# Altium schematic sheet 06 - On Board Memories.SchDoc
size B; CompanyName: Microchip Technology Inc.; Organization: Microchip Technology; Address1: 2355 West Chandler Blvd.; Address2: Chandler, AZ  85224; Address4: USA; DocumentNumber: 6; SheetNumber: 6; SheetTotal: 13; SheetTitle: On Board Memories
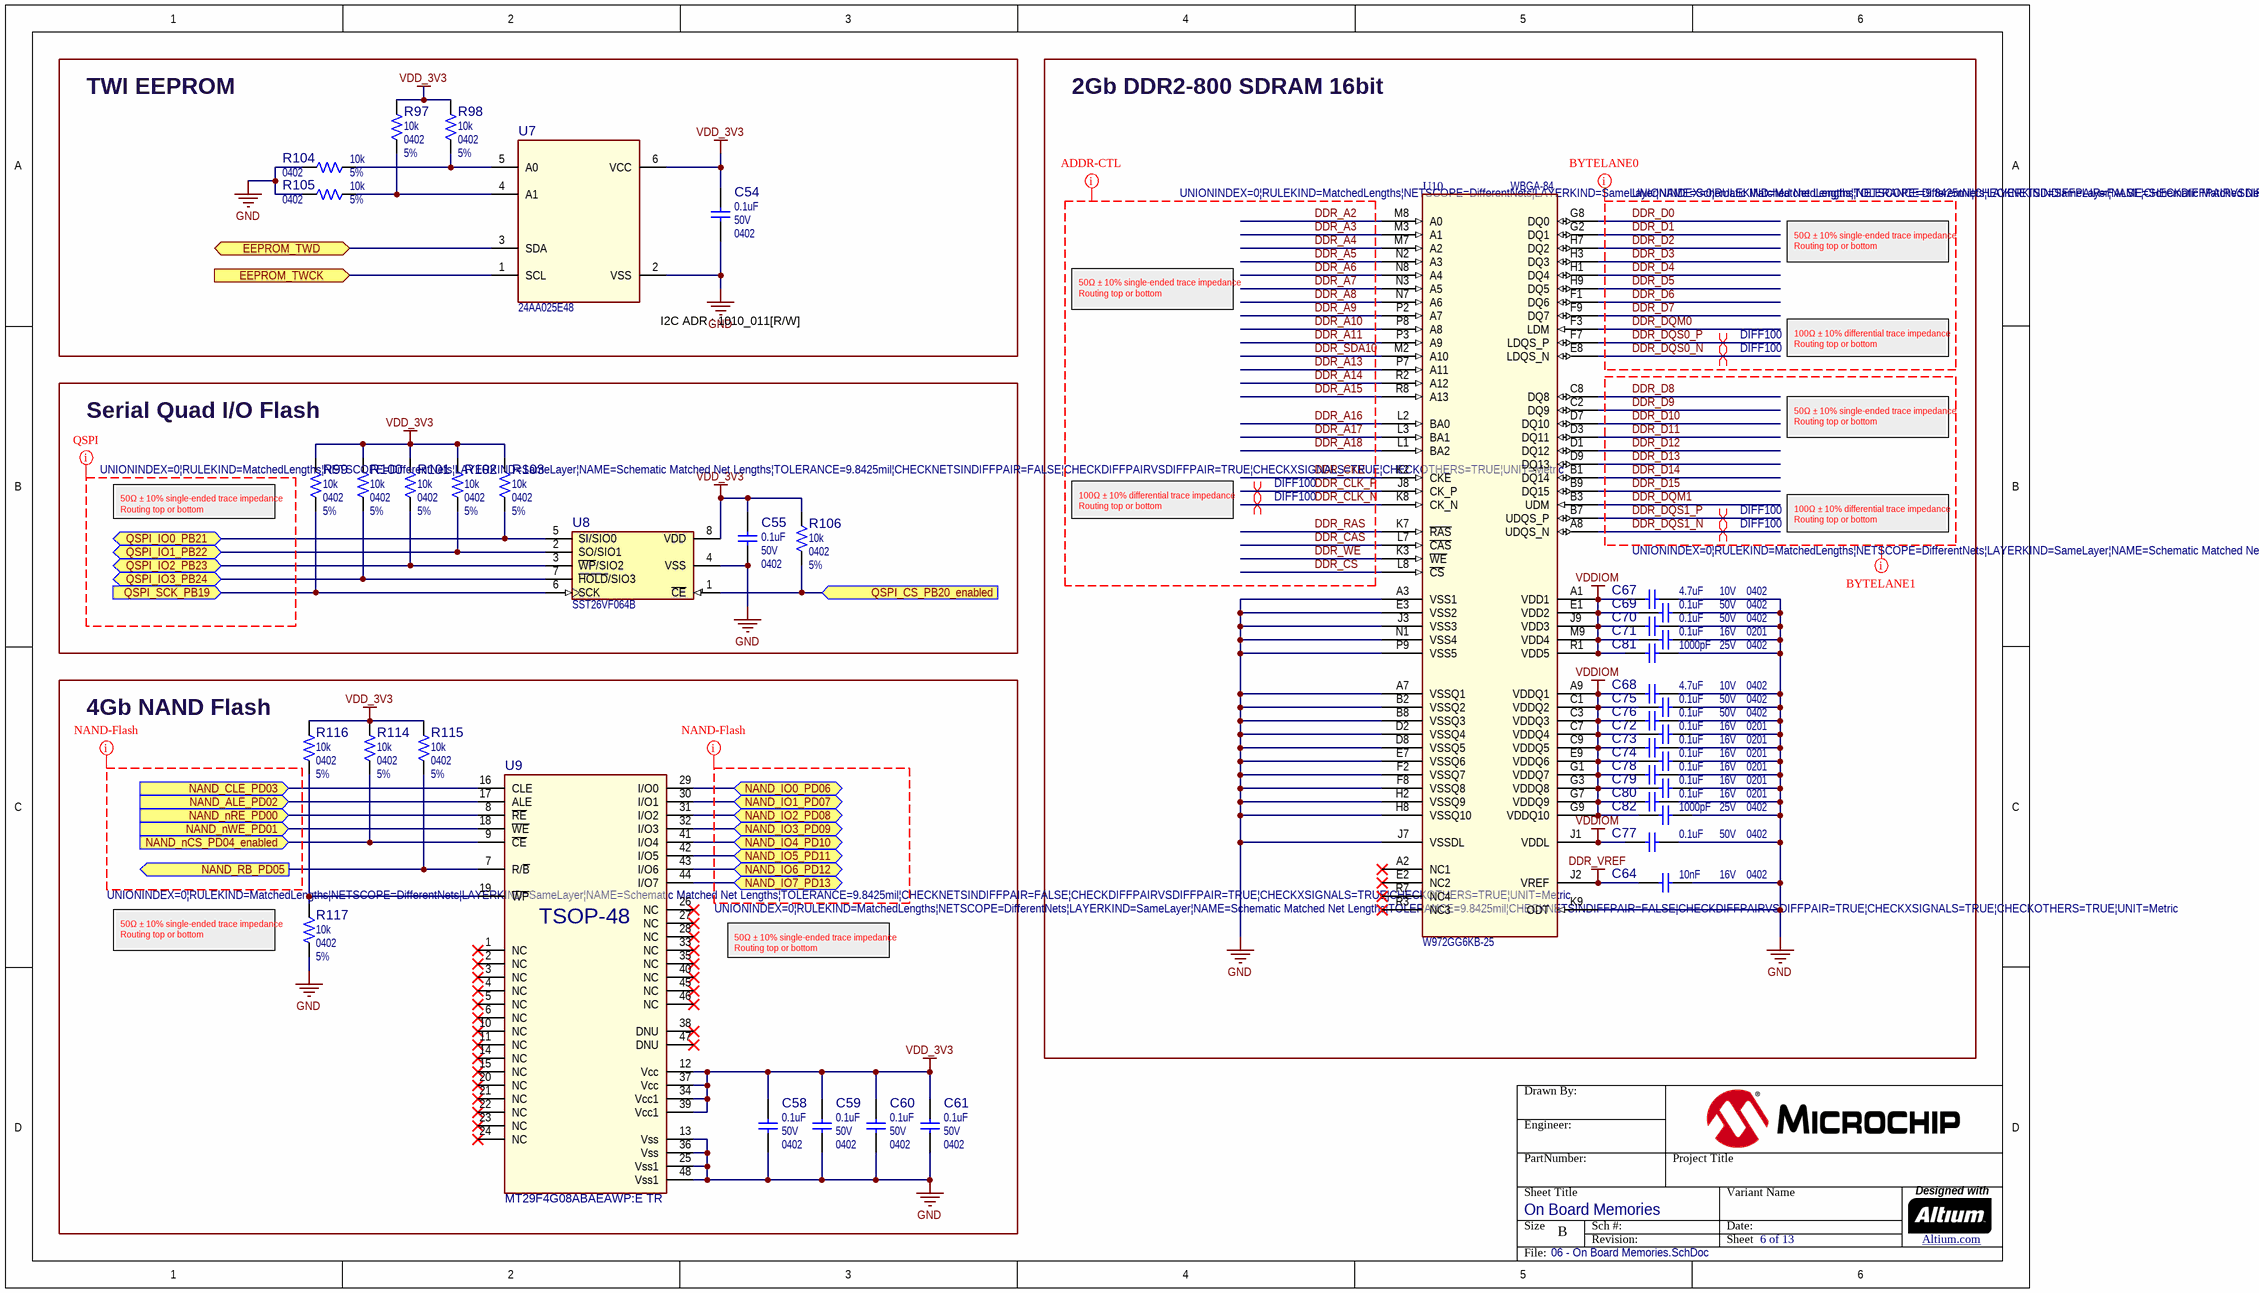
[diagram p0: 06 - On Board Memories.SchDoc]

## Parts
?  (no value)  (graphical)
C54  value 0.1uF  Voltage: 50V  Package: 0402  [CAP_C_0402]  (hidden comment: Capacitor NP)
C55  value 0.1uF  Voltage: 50V  Package: 0402  [CAP_C_0402]  (hidden comment: Capacitor NP)
C58  value 0.1uF  Voltage: 50V  Package: 0402  [CAP_C_0402]  (hidden comment: Capacitor NP)
C59  value 0.1uF  Voltage: 50V  Package: 0402  [CAP_C_0402]  (hidden comment: Capacitor NP)
C60  value 0.1uF  Voltage: 50V  Package: 0402  [CAP_C_0402]  (hidden comment: Capacitor NP)
C61  value 0.1uF  Voltage: 50V  Package: 0402  [CAP_C_0402]  (hidden comment: Capacitor NP)
C64  value 10nF  Voltage: 16V  Package: 0402  [CAP_C_0402]  (hidden comment: Capacitor NP)
C67  value 4.7uF  Voltage: 10V  Package: 0402  [CAP_C_0402]  (hidden comment: Capacitor NP)
C68  value 4.7uF  Voltage: 10V  Package: 0402  [CAP_C_0402]  (hidden comment: Capacitor NP)
C69  value 0.1uF  Voltage: 50V  Package: 0402  [CAP_C_0402]  (hidden comment: Capacitor NP)
C70  value 0.1uF  Voltage: 50V  Package: 0402  [CAP_C_0402]  (hidden comment: Capacitor NP)
C71  value 0.1uF  Voltage: 16V  Package: 0201  [CAP_C_0201]  (hidden comment: Capacitor NP)
C72  value 0.1uF  Voltage: 16V  Package: 0201  [CAP_C_0201]  (hidden comment: Capacitor NP)
C73  value 0.1uF  Voltage: 16V  Package: 0201  [CAP_C_0201]  (hidden comment: Capacitor NP)
C74  value 0.1uF  Voltage: 16V  Package: 0201  [CAP_C_0201]  (hidden comment: Capacitor NP)
C75  value 0.1uF  Voltage: 50V  Package: 0402  [CAP_C_0402]  (hidden comment: Capacitor NP)
C76  value 0.1uF  Voltage: 50V  Package: 0402  [CAP_C_0402]  (hidden comment: Capacitor NP)
C77  value 0.1uF  Voltage: 50V  Package: 0402  [CAP_C_0402]  (hidden comment: Capacitor NP)
C78  value 0.1uF  Voltage: 16V  Package: 0201  [CAP_C_0201]  (hidden comment: Capacitor NP)
C79  value 0.1uF  Voltage: 16V  Package: 0201  [CAP_C_0201]  (hidden comment: Capacitor NP)
C80  value 0.1uF  Voltage: 16V  Package: 0201  [CAP_C_0201]  (hidden comment: Capacitor NP)
C81  value 1000pF  Voltage: 25V  Package: 0402  [CAP_C_0402]  (hidden comment: Capacitor NP)
C82  value 1000pF  Voltage: 25V  Package: 0402  [CAP_C_0402]  (hidden comment: Capacitor NP)
R97  value 10k  Package: 0402  Tolerance: 5%  [RES_C_0402]  (hidden comment: Resistor)
R98  value 10k  Package: 0402  Tolerance: 5%  [RES_C_0402]  (hidden comment: Resistor)
R99  value 10k  Package: 0402  Tolerance: 5%  [RES_C_0402]  (hidden comment: Resistor)
R100  value 10k  Package: 0402  Tolerance: 5%  [RES_C_0402]  (hidden comment: Resistor)
R101  value 10k  Package: 0402  Tolerance: 5%  [RES_C_0402]  (hidden comment: Resistor)
R102  value 10k  Package: 0402  Tolerance: 5%  [RES_C_0402]  (hidden comment: Resistor)
R103  value 10k  Package: 0402  Tolerance: 5%  [RES_C_0402]  (hidden comment: Resistor)
R104  value 10k  Package: 0402  Tolerance: 5%  [RES_C_0402]  (hidden comment: Resistor)
R105  value 10k  Package: 0402  Tolerance: 5%  [RES_C_0402]  (hidden comment: Resistor)
R106  value 10k  Package: 0402  Tolerance: 5%  [RES_C_0402]  (hidden comment: Resistor)
R114  value 10k  Package: 0402  Tolerance: 5%  [RES_C_0402]  (hidden comment: Resistor)
R115  value 10k  Package: 0402  Tolerance: 5%  [RES_C_0402]  (hidden comment: Resistor)
R116  value 10k  Package: 0402  Tolerance: 5%  [RES_C_0402]  (hidden comment: Resistor)
R117  value 10k  Package: 0402  Tolerance: 5%  [RES_C_0402]  (hidden comment: Resistor)
U7  value 24AA025E48  [SOT-23-6]  (hidden comment: 24XXXX SOT-23-6)
U8  value SST26VF064B  [SOIJ-8]  (hidden comment: SST26VFXXX SOIC-8_WSON-8_SOIJ-8)
U9  value MT29F4G08ABAEAWP:E TR  Package: TSOP-48  [TSOP-48_P0.5]  (hidden comment: MT29F4G08ABA TSOP-48)
U10  value W972GG6KB-25  Package: WBGA-84  [WBGA-84_P0.8_8x12.5x1.2]  (hidden comment: W972GG6KB-25 WBGA-84)

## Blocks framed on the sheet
TWI EEPROM: C54 R97 R98 R104 R105 U7
2Gb DDR2-800 SDRAM 16bit: C64 C67-C82 U10
Serial Quad I/O Flash: C55 R99-R103 R106 U8
4Gb NAND Flash: C58-C61 R114-R117 U9

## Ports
EEPROM_TWCK (in), EEPROM_TWD (bidir), NAND_ALE_PD02 (in), NAND_CLE_PD03 (in), NAND_IO0_PD06 (bidir), NAND_IO1_PD07 (bidir), NAND_IO2_PD08 (bidir), NAND_IO3_PD09 (bidir), NAND_IO4_PD10 (bidir), NAND_IO5_PD11 (bidir), NAND_IO6_PD12 (bidir), NAND_IO7_PD13 (bidir), NAND_nCS_PD04_enabled (in), NAND_nRE_PD00 (in), NAND_nWE_PD01 (in), NAND_RB_PD05 (out), QSPI_CS_PB20_enabled (in), QSPI_IO0_PB21 (bidir), QSPI_IO1_PB22 (bidir), QSPI_IO2_PB23 (bidir), QSPI_IO3_PB24 (bidir), QSPI_SCK_PB19 (in)

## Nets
DDR_VREF: C64.1 U10.J2(VREF)
GND: C54.2 C55.2 C58.2 C59.2 C60.2 C61.2 C64.2 C67.1 C68.1 C69.2 C70.2 C71.1 C72.1 C73.1 C74.1 C75.2 C76.2 C77.2 C78.1 C79.1 C80.1 C81.1 C82.1 R104.2 R105.2 R117.1 U7.2(VSS) U8.4(VSS) U9.13(Vss) U9.25(Vss1) U9.36(Vss) U9.48(Vss1) U10.A3(VSS1) U10.A7(VSSQ1) U10.B2(VSSQ2) U10.B8(VSSQ3) U10.D2(VSSQ4) U10.D8(VSSQ5) U10.E3(VSS2) U10.E7(VSSQ6) U10.F2(VSSQ7) U10.F8(VSSQ8) U10.H2(VSSQ9) U10.H8(VSSQ10) U10.J3(VSS3) U10.J7(VSSDL) U10.K9(ODT) U10.N1(VSS4) U10.P9(VSS5)
VDD_3V3: C54.1 C55.1 C58.1 C59.1 C60.1 C61.1 R97.2 R98.2 R99.2 R100.2 R101.2 R102.2 R103.2 R106.2 R114.2 R115.2 R116.2 U7.6(VCC) U8.8(VDD) U9.12(Vcc) U9.34(Vcc1) U9.37(Vcc) U9.39(Vcc1)
VDDIOM: C67.2 C68.2 C69.1 C70.1 C71.2 C72.2 C73.2 C74.2 C75.1 C76.1 C77.1 C78.2 C79.2 C80.2 C81.2 C82.2 U10.A1(VDD1) U10.A9(VDDQ1) U10.C1(VDDQ2) U10.C3(VDDQ3) U10.C7(VDDQ4) U10.C9(VDDQ5) U10.E1(VDD2) U10.E9(VDDQ6) U10.G1(VDDQ7) U10.G3(VDDQ8) U10.G7(VDDQ9) U10.G9(VDDQ10) U10.J1(VDDL) U10.J9(VDD3) U10.M9(VDD4) U10.R1(VDD5)
DDR_A2: U10.M8(A0)
DDR_A3: U10.M3(A1)
DDR_A4: U10.M7(A2)
DDR_A5: U10.N2(A3)
DDR_A6: U10.N8(A4)
DDR_A7: U10.N3(A5)
DDR_A8: U10.N7(A6)
DDR_A9: U10.P2(A7)
DDR_A10: U10.P8(A8)
DDR_A11: U10.P3(A9)
DDR_A13: U10.P7(A11)
DDR_A14: U10.R2(A12)
DDR_A15: U10.R8(A13)
DDR_A16: U10.L2(BA0)
DDR_A17: U10.L3(BA1)
DDR_A18: U10.L1(BA2)
DDR_CAS: U10.L7(~{CAS})
DDR_CKE: U10.K2(CKE)
DDR_CLK_N: U10.K8(CK_N)
DDR_CLK_P: U10.J8(CK_P)
DDR_CS: U10.L8(~{CS})
DDR_D0: U10.G8(DQ0)
DDR_D1: U10.G2(DQ1)
DDR_D2: U10.H7(DQ2)
DDR_D3: U10.H3(DQ3)
DDR_D4: U10.H1(DQ4)
DDR_D5: U10.H9(DQ5)
DDR_D6: U10.F1(DQ6)
DDR_D7: U10.F9(DQ7)
DDR_D8: U10.C8(DQ8)
DDR_D9: U10.C2(DQ9)
DDR_D10: U10.D7(DQ10)
DDR_D11: U10.D3(DQ11)
DDR_D12: U10.D1(DQ12)
DDR_D13: U10.D9(DQ13)
DDR_D14: U10.B1(DQ14)
DDR_D15: U10.B9(DQ15)
DDR_DQM0: U10.F3(LDM)
DDR_DQM1: U10.B3(UDM)
DDR_DQS0_N: U10.E8(LDQS_N)
DDR_DQS0_P: U10.F7(LDQS_P)
DDR_DQS1_N: U10.A8(UDQS_N)
DDR_DQS1_P: U10.B7(UDQS_P)
DDR_RAS: U10.K7(~{RAS})
DDR_SDA10: U10.M2(A10)
DDR_WE: U10.K3(~{WE})
EEPROM_TWCK: U7.1(SCL) ; port EEPROM_TWCK
EEPROM_TWD: U7.3(SDA) ; port EEPROM_TWD
NAND_ALE_PD02: U9.17(ALE) ; port NAND_ALE_PD02
NAND_CLE_PD03: U9.16(CLE) ; port NAND_CLE_PD03
NAND_IO0_PD06: U9.29(I/O0) ; port NAND_IO0_PD06
NAND_IO1_PD07: U9.30(I/O1) ; port NAND_IO1_PD07
NAND_IO2_PD08: U9.31(I/O2) ; port NAND_IO2_PD08
NAND_IO3_PD09: U9.32(I/O3) ; port NAND_IO3_PD09
NAND_IO4_PD10: U9.41(I/O4) ; port NAND_IO4_PD10
NAND_IO5_PD11: U9.42(I/O5) ; port NAND_IO5_PD11
NAND_IO6_PD12: U9.43(I/O6) ; port NAND_IO6_PD12
NAND_IO7_PD13: U9.44(I/O7) ; port NAND_IO7_PD13
NAND_nCS_PD04_enabled: R114.1 U9.9(~{CE}) ; port NAND_nCS_PD04_enabled
NAND_nRE_PD00: U9.8(~{RE}) ; port NAND_nRE_PD00
NAND_nWE_PD01: U9.18(~{WE}) ; port NAND_nWE_PD01
NAND_RB_PD05: R115.1 U9.7(R/~{B}) ; port NAND_RB_PD05
QSPI_CS_PB20_enabled: R106.1 U8.1(~{CE}) ; port QSPI_CS_PB20_enabled
QSPI_IO0_PB21: R103.1 U8.5(SI/SIO0) ; port QSPI_IO0_PB21
QSPI_IO1_PB22: R102.1 U8.2(SO/SIO1) ; port QSPI_IO1_PB22
QSPI_IO2_PB23: R101.1 U8.3(~{WP}/SIO2) ; port QSPI_IO2_PB23
QSPI_IO3_PB24: R100.1 U8.7(~{HOLD}/SIO3) ; port QSPI_IO3_PB24
QSPI_SCK_PB19: R99.1 U8.6(SCK) ; port QSPI_SCK_PB19
NetR97_1: R97.1 R105.1 U7.4(A1)
NetR98_1: R98.1 R104.1 U7.5(A0)
NetR116_1: R116.1 R117.2 U9.19(~{WP})

Not connected (* = marked no-connect by the designer): U9 1(NC)* 2(NC)* 3(NC)* 4(NC)* 5(NC)* 6(NC)* 10(NC)* 11(NC)* 14(NC)* 15(NC)* 20(NC)* 21(NC)* 22(NC)* 23(NC)* 24(NC)* 26(NC)* 27(NC)* 28(NC)* 33(NC)* 35(NC)* 38(DNU)* 40(NC)* 45(NC)* 46(NC)* 47(DNU)*; U10 A2(NC1)* E2(NC2)* R3(NC3)* R7(NC4)*

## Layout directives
net class NAND-Flash; rule Matched Net Lengths [Tolerance = 0.25mm]: (no net found under the mark)
net class DDR-LANE0; rule Matched Net Lengths [Tolerance = 0.25mm]: DDR_D0, DDR_D1, DDR_D2, DDR_D3, DDR_D4, DDR_D5, DDR_D6, DDR_D7, DDR_DQM0, DDR_DQS0_N, DDR_DQS0_P
net class DDR-ADD-CTL; rule Matched Net Lengths [Tolerance = 0.25mm]: DDR_A2, DDR_A3, DDR_A4, DDR_A5, DDR_A6, DDR_A7, DDR_A8, DDR_A9, DDR_A10, DDR_A11, DDR_A13, DDR_A14, DDR_A15, DDR_A16, DDR_A17, DDR_A18, DDR_CAS, DDR_CKE, DDR_CLK_N, DDR_CLK_P, DDR_CS, DDR_RAS, DDR_SDA10, DDR_WE
net class DDR-LANE1; rule Matched Net Lengths [Tolerance = 0.25mm]: DDR_D8, DDR_D9, DDR_D10, DDR_D11, DDR_D12, DDR_D13, DDR_D14, DDR_D15, DDR_DQM1, DDR_DQS1_N, DDR_DQS1_P
differential pair; differential pair class DIFF100; net class DIFF100; rule Matched Net Lengths [Tolerance = 10mil]: DDR_CLK_N, DDR_CLK_P, DDR_DQS0_N, DDR_DQS0_P, DDR_DQS1_N, DDR_DQS1_P
net class Q-SPI; rule Matched Net Lengths [Tolerance = 0.25mm]: (no net found under the mark)

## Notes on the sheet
- 50Ω ± 10% single-ended trace impedance
  Routing top or bottom
- (near U7) I2C ADR : 1010_011[R/W]
- 100Ω ± 10% differential trace impedance
  Routing top or bottom
- (near R99) 50Ω ± 10% single-ended trace impedance
  Routing top or bottom
- (near R117) 50Ω ± 10% single-ended trace impedance
  Routing top or bottom

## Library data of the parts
? = Title Block B
C54 C55 C58-C61 = CAP1463: Capacitor; Manufacturer 1: TDK Corporation; Manufacturer Part Number 1: C1005X7R1H104K050BB; Description_: CAP CER 0.1uF 50V 10% X7R SMD 0402; Dev Tools Status: Production; Tolerance: 10%; Temperature Coeffcient: X7R; Type: Ceramic; Populated: YES; Owner: Jamus Griego
C64 = CAP0278: Capacitor; Manufacturer 1: KEMET; Manufacturer Part Number 1: C0402C103K4RACTU; Description_: CAP CER 10000pF 16V 10% X7R SMD 0402; Dev Tools Status: Production; Tolerance: 10%; Temperature Coeffcient: X7R; Type: Ceramic; Populated: YES
C67 C68 = CAP1684: Capacitor; Manufacturer 1: TDK Corporation; Manufacturer Part Number 1: C1005X5R1A475K050BC; Description_: CAP CER 4.7uF 10V 10% X5R SMD 0402; Dev Tools Status: Production; Tolerance: 10%; Temperature Coeffcient: X5R; Type: Ceramic; Owner: Jesus Aviles; Populated: YES
C69 C70 C75-C77 = CAP1463: Capacitor; Manufacturer 1: TDK Corporation; Manufacturer Part Number 1: C1005X7R1H104K050BB; Description_: CAP CER 0.1uF 50V 10% X7R SMD 0402; Dev Tools Status: Production; Tolerance: 10%; Temperature Coeffcient: X7R; Type: Ceramic; Owner: Jamus Griego; Populated: YES
C71-C74 C78-C80 = CAP1203: Capacitor; Manufacturer 1: Murata; Manufacturer Part Number 1: GRM033R61C104KE84D; Description_: CAP CER 0.1uF 16V 10% X5R SMD 0201; Dev Tools Status: Production; Tolerance: 10%; Temperature Coeffcient: X5R; Type: Ceramic; Owner: Tad Ahlvers; Populated: YES
C81 C82 = CAP0566: Capacitor; Manufacturer 1: TDK; Manufacturer Part Number 1: C1005C0G1E102J; Description_: CAP CER 1000pF 25V 5% C0G SMD 0402; Dev Tools Status: Production; Tolerance: 5%; Temperature Coeffcient: C0G; Type: Ceramic; Populated: Yes
R97 R98 R106 R114-R116 = RSMT0439: Manufacturer 1: Vishay; Manufacturer Part Number 1: CRCW040210K0JNED; Description_: RES TKF 10k 5% 1/16W SMD 0402; Dev Tools Status: Production; Voltage: 50V; Temperature Coeffcient: 100ppm/C; Power: 1/16W; Populated: Yes
R99-R105 R117 = RSMT0439: Manufacturer 1: Vishay; Manufacturer Part Number 1: CRCW040210K0JNED; Description_: RES TKF 10k 5% 1/16W SMD 0402; Dev Tools Status: Production; Voltage: 50V; Temperature Coeffcient: 100ppm/C; Power: 1/16W; Populated: DNP
U7 = MIC7407: Manufacturer 1: Microchip Technology; Manufacturer Part Number 1: 24AA025E48T-I/OT; Description_: MCHP MEMORY SERIAL EEPROM 2Kb I2C 24AA025E48T-I/OT SOT-23-6; MAPS Description: 24AA025E48 device, which will be a pre-prog. version of the 24AA024H (DFAX7).; Dev Tools Status: Design; Owner: Ciprian Abramov; MPC: DFAX7TC8XD00; PackingMedia: T/R; TempRange: -40C to +85C; Stage: REL; LeadCount: 6; ForceMinOrderQtyMult: True; MinOrderQty: 50; LeadContent: Pb-FREE; MemorySize: 2K; OpVoltMin: 1.7; OpVoltMax: 5.5; MaxClockFreq: 400 kHz; AddressPins: 3; PageSize_B: 16; WPScheme: Half Array; MemoryOrg: x8; Endurance: 1,000,000; Comments: memory size changed from 2KBits to 2K; Populated: YES
U8 = MIC6216: SQI Serial Flash; Manufacturer 1: Microchip Technology; Manufacturer Part Number 1: SST26VF064B-104I/SM; Description_: MCHP SERIAL FLASH SST26VF064B-104I/SM SOIJ-8; MAPS Description: 64Mb 2.3V TO 3.6V SQI Flash Memory; Dev Tools Status: Production; Owner: Sompoch Loboonlert; MPC: S01027C3XA23; PackingMedia: TUBE; TempRange: -40C to +85C; Stage: REL; LeadCount: 8; PackageWidth: .208in; ForceMinOrderQtyMult: False; MinOrderQty: 0; LeadContent: Pb-FREE; Busmodes: SPI,SDI,SQI; MemorySize: 64Mb; OpVoltMin: 2,3; OpVoltMax: 3,6; MaxClockFreq: 104 MHz; PageSize_B: 256; WPScheme: Full Array; Endurance: 100,000; Populated: YES
U9 = IC1477: Manufacturer 1: Micron Technology Inc.; MCHP-ID: IC1477; Description_: IC MEMORY MT29F4G08ABAEAWP:E TR FLASH 4GBIT TSOP-48; Dev Tools Status: Design; Vin: 2.7 V to 3.6 V; Owner: Ilie Galan; Populated: YES
U10 = IC1476: 2Gb DDR2-800 SDRAM, 128Mb x 16; Manufacturer 1: Winbond Electronics; MCHP-ID: IC1476; Description_: IC MEMORY W972GG6KB-25 SDRAM 2Gb 800MHz WBGA-84; Dev Tools Status: Design; Vin: 1.7V to 1.9V; Owner: Ciprian Abramov; Populated: YES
